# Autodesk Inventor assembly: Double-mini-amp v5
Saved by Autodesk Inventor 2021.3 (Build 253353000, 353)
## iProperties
Created: 2022-07
Part Number: Double-mini-amp v5
Document SubType Name: Assembly
Designer: Administrator
Title: Double-mini-amp v5
Author: Administrator
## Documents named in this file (4)
- c:\worker\convert-fusion-r04\tmp\job-1\186\output\files\05ef811f-4573-476e-8ba5-de3f58aa0f0a\Double-mini-amp v5.iam
- c:\worker\convert-fusion-r04\tmp\job-1\186\output\files\05ef811f-4573-476e-8ba5-de3f58aa0f0a\Mini-Amp-64 v1.ipt
- c:\worker\convert-fusion-r04\tmp\job-1\186\output\files\05ef811f-4573-476e-8ba5-de3f58aa0f0a\Mini-Amp-64 v1 (1).ipt
- c:\worker\convert-fusion-r04\tmp\job-1\186\output\files\05ef811f-4573-476e-8ba5-de3f58aa0f0a\dual adapter v2.ipt
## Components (3 placed, 3 different names)
1. Mini-Amp-64 v1:1
2. Mini-Amp-64 v1 (1):1
3. dual adapter v2:1
